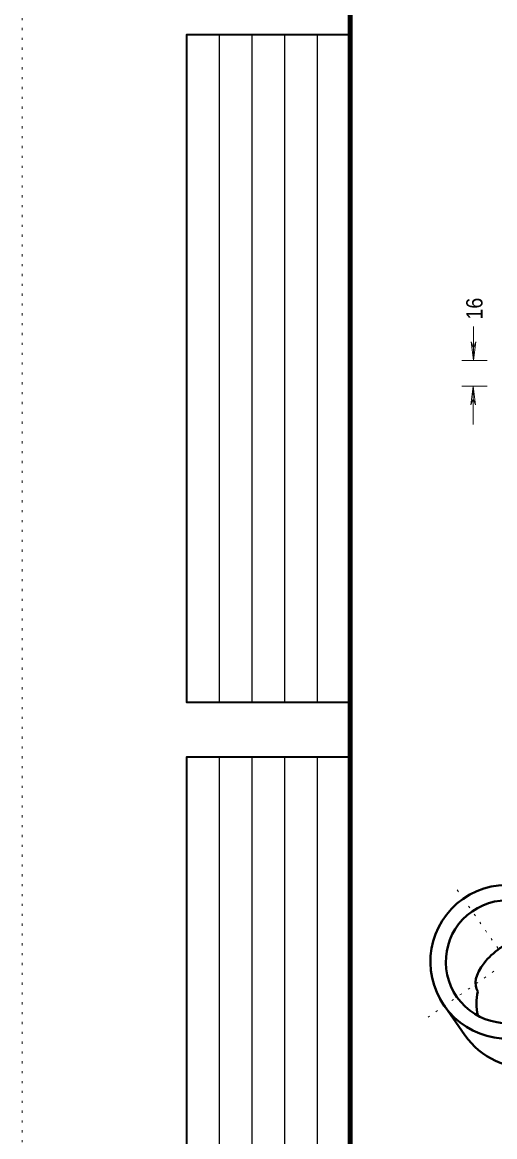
# Model space of a CAD drawing. Extents: x 312583 to 312854, y 144419 to 144597.
# Drawn here: x 312601.2 to 312623.3, y 144470.4 to 144522.4 of the extents above; entities that cross this region are included whole.
import ezdxf

# ---------------------------------------------------------------- set-up
doc = ezdxf.new("R2010")
doc.units = 0
doc.header["$LTSCALE"] = 0.3
doc.linetypes.add('DOTTED', pattern=[1.5, 0.3, -1.2])
for name, color, linetype, lineweight in [('1', 7, 'Continuous', 40), ('2', 7, 'Continuous', 13), ('62', 7, 'DOTTED', 13)]:
    doc.layers.add(name, color=color, linetype=linetype, lineweight=lineweight)

msp = doc.modelspace()

# ---------------------------------------------------------------- linework, layer by layer
at = {"layer": '1', "lineweight": 25}
for p, q in [((312610.4087, 144490.6573), (312610.4087, 144521.8756)), ((312611.9315, 144490.6573), (312611.9315, 144521.8756)), ((312613.4543, 144490.6573), (312613.4543, 144521.8756)), ((312614.9772, 144490.6573), (312614.9772, 144521.8756)), ((312610.4087, 144456.901), (312610.4087, 144488.1192)), ((312611.9315, 144456.901), (312611.9315, 144488.1192)), ((312613.4543, 144456.901), (312613.4543, 144488.1192)), ((312614.9772, 144456.901), (312614.9772, 144488.1192))]:
    msp.add_line(p, q, dxfattribs=at)
at = {"layer": '1'}
msp.add_line((312621.8606, 144475.1016), (312620.9023, 144476.4739), dxfattribs=at)
at = {"layer": '1', "lineweight": 158}
msp.add_lwpolyline([(312616.5, 144423.1446), (312616.5, 144585.0846), (312849, 144585.0846)], dxfattribs=at)
at = {"layer": '1', "lineweight": 35}
for points in [[(312616.5, 144490.6573), (312608.8858, 144490.6573), (312608.8858, 144521.8756), (312616.5, 144521.8756)], [(312616.5, 144456.901), (312608.8858, 144456.901), (312608.8858, 144488.1192), (312616.5, 144488.1192)]]:
    msp.add_lwpolyline(points, dxfattribs=at)
at = {"layer": '1'}
for major_axis, ratio in [((-2.9425, -2.0626), 0.999869), ((-2.3521, -1.6486), 0.999836)]:
    msp.add_ellipse((312623.8424, 144478.5382), major_axis=major_axis, ratio=ratio, dxfattribs=at)
for centre, major_axis, ratio, start_param, end_param in [((312624.0993, 144478.2852), (-1.6368, -1.1251), 0.537251, 3.1255912, 6.2961342), ((312624.8046, 144477.1658), (-2.9425, -2.0626), 0.999869, 0.0001305, 3.1417232), ((312625.2761, 144476.5716), (-2.3521, -1.6486), 0.999836, 5.4703118, 5.8646097)]:
    msp.add_ellipse(centre, major_axis=major_axis, ratio=ratio, start_param=start_param, end_param=end_param, dxfattribs=at)
at = {"layer": '2'}
for p, q in [((312622.2665, 144506.642), (312622.2665, 144508.2275)), ((312622.1591, 144507.5084), (312622.2665, 144507.2324)), ((312622.2665, 144506.642), (312622.1591, 144507.5084)), ((312622.3738, 144507.5084), (312622.2665, 144507.2324)), ((312622.2665, 144506.642), (312622.3738, 144507.5084)), ((312621.7221, 144506.642), (312622.892, 144506.642)), ((312621.7221, 144505.4384), (312622.892, 144505.4384)), ((312622.2435, 144505.4384), (312622.1361, 144504.572)), ((312622.2435, 144503.653), (312622.2435, 144505.4384)), ((312622.2435, 144505.4384), (312622.3508, 144504.572)), ((312622.1361, 144504.572), (312622.2435, 144504.848)), ((312622.3508, 144504.572), (312622.2435, 144504.848))]:
    msp.add_line(p, q, dxfattribs=at)
at = {"layer": '2', "linetype": 'DOTTED'}
for p, q in [((312623.4016, 144479.1726), (312621.3009, 144482.1779)), ((312623.2176, 144478.0992), (312620.1509, 144475.9526))]:
    msp.add_line(p, q, dxfattribs=at)
at = {"layer": '62'}
msp.add_line((312601.2, 144418.5846), (312601.2, 144596.7846), dxfattribs=at)

# ---------------------------------------------------------------- texts
at = {"layer": '2', "width": 0.9}
msp.add_text('16', height=0.76, rotation=90, dxfattribs=at).set_placement((312622.6823, 144508.5551))

doc.saveas('drawing.dxf')
